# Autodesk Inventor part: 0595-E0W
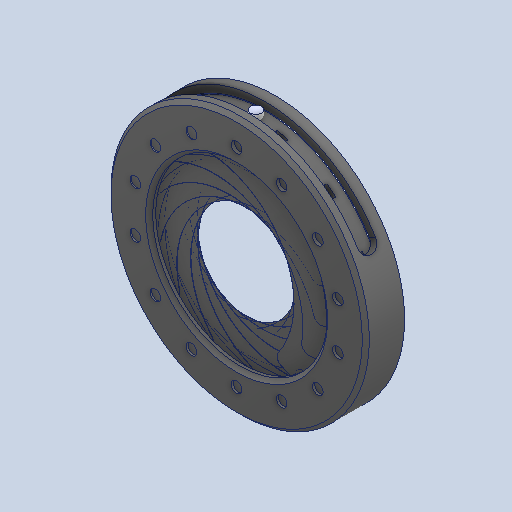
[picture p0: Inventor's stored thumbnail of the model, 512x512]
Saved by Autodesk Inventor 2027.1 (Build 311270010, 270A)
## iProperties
Created: 2023-02
Part Number: 0595-E0W
Material: Generic
Description: STEP AP214
Document SubType Name: Modeling
Designer: dunge
Density: 1 g/cm^3
Appearance: Default
Title: 0595-E0W.STEP
Revision Number: ANY
Sending System: SolidWorks 2022
Preprocessor: SwSTEP 2.0
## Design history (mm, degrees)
feature "700-370 Outer Ring-1-solid1"
feature "700-370 Inner Ring-1-solid1"
feature "700-370 Blade-1-solid1"
feature "700-370 Blade-2-solid1"
feature "700-370 Blade-3-solid1"
feature "700-370 Blade-4-solid1"
feature "700-370 Blade-5-solid1"
feature "700-370 Blade-6-solid1"
feature "700-198 Lever-1-solid1"
feature "700-370 Blade-7-solid1"
feature "700-370 Blade-8-solid1"
feature "700-370 Blade-9-solid1"
feature "700-370 Blade-10-solid1"
feature "700-370 Blade-11-solid1"
feature "700-370 Blade-12-solid1"
feature "700-370 Blade-13-solid1"
feature "700-370 Blade-14-solid1"
sketch "Sketch1"
  geometry: C1 r 1.755 at (0, 0); 2 further points
  constraints: 1 centre point, 1 coincident
extrude "Extrusion1" cut sketch "Sketch1" distance "d0" = 25.4; taper "d1" = 0 deg
body "Solid1"
body "Solid2"
body "Solid3"
body "Solid4"
body "Solid5"
body "Solid6"
body "Solid7"
body "Solid8"
body "Solid9"
body "Solid10"
body "Solid11"
body "Solid12"
body "Solid13"
body "Solid14"
body "Solid15"
body "Solid16"
body "Solid17"
